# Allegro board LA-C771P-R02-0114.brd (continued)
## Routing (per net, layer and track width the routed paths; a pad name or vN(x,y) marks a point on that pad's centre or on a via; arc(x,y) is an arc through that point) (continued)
PMC_PCIE_WAKE#: length 22.5
  TOP w0.102: QC3.3 85.16,78.31 88.38,75.09 v2(89.97,75.09) 91.21,73.86 96.69,73.86 96.87,74.03 100.15,74.03 100.21,73.97 100.75,73.97 101,74.22 101,75.19 99.78,76.41 RPC5.1 99.78,76.84 100.05,77.11 v3(100.05,77.39)
  BOTTOM w0.102: UC4.F26 100.05,77.78 v3(100.05,77.39)
PMC_PLTRST#: length 118.8
  TOP w0.102: QC2.3 88.83,28.54 v1(88.83,30.25) v3(88.83,31.4) ; UC8.1 UC8.2 79,81.57 79.73,82.3 80.3,82.3 81.03,81.56 RC48.1 81.03,81.04 v3(80.75,80.76)
  IN2 w0.127: v3(80.75,80.76) 80.9,80.76 81.82,79.84 83.48,79.84 83.89,79.43 86.41,79.43 89.48,82.5 93.05,82.5 93.99,83.45 94.88,83.45 95.92,82.41 99.09,82.41 100.55,80.94 v3(100.55,80.28)
  BOTTOM w0.102: v3(100.55,80.28) 100.19,80.65 UC4.F20 ; v3(80.75,80.76) 80.7,80.7 79.83,80.7 79.29,80.16 77.66,80.16 77.04,80.78 74.37,80.78 73.71,80.12 71.65,80.12 70.81,79.28 70.81,76.59 69.94,75.72 69.94,72.93 71.81,71.06 71.81,57.54 63.48,49.21 63.48,45.27 62.27,44.06 62.27,39.78 66.31,35.74 70.16,35.74 71.28,34.63 82.38,34.63 85.14,31.86 88.37,31.86 v3(88.83,31.4)
PMC_PLTRST#_R: length 67.5
  TOP w0.102: v3(70.45,71.07) 71.1,71.07 71.76,70.4 73.8,70.4 77.01,73.61 77.01,75.33 77.28,75.6 77.28,78.34 78.3,79.37 79.13,79.37 80.12,80.36 RC48.2 ; RB30.1 72.8,33.89 v3(72.55,34.14)
  BOTTOM w0.102: v3(72.55,34.14) v2(71.51,34.14) 71.08,34.14 69.96,35.26 66.11,35.26 61.79,39.58 61.79,44.26 63,45.47 63,49.41 71.33,57.74 71.33,70.19 v3(70.45,71.07)
PMC_SLP_S3#: length 138.4
  TOP w0.102: UB1.106 78.27,17.37 78.27,17.37 78.07,17.37 v3(77.18,18.25) ; v3(96.55,20.71) 96.83,20.99 96.83,24.8 95.88,25.75 95.88,28.87 v3(93.99,30.76)
  IN2 w0.127: v3(96.55,20.71) 96.5,20.76 90.66,20.76 89.8,21.62 88.55,21.62 86.91,19.99 86.13,19.99 85.83,19.68 78.63,19.68 77.2,18.25 v3(77.18,18.25)
  BOTTOM w0.102: v3(93.99,30.76) 92.41,32.34 89.6,32.34 87.65,34.29 84.9,34.29 83.27,35.92 71.74,35.92 70.72,36.94 67.17,36.94 65.31,38.79 65.31,40.27 64.05,41.53 64.05,43.32 65.31,44.58 65.31,45.69 66.24,46.62 66.24,48.01 74.56,56.32 74.56,74.23 74.03,74.76 74.03,75.67 75.84,77.48 85.22,77.48 v1(86.71,78.98) 88.62,80.88 91.46,80.88 91.59,80.75 92.39,80.75 93.08,80.07 94.33,80.07 95.02,79.38 96.22,79.38 96.65,78.95 97.15,78.95 97.31,79.11 98.01,79.11 98.15,79.26 98.3,79.26 98.45,79.1 98.62,79.1 98.71,79.12 98.81,79.19 98.89,79.32 98.94,79.32 99.51,79.89 UC4.D22
PMC_SLP_S4#: length 111.6
  TOP w0.102: RB22.1 83.67,24.99 84.74,24.99 85.2,25.45 85.2,26.08 84.6,26.68 v1(84.6,27.5) 84.6,32.53 85.71,33.64 86.49,33.64 v3(86.82,33.31)
  IN2 w0.127: v3(99.83,79.42) 99.76,79.42 98.7,80.48 98.7,81.4 98,82.1 95.69,82.1 95.21,82.58 94.02,82.58 93.43,82 89.69,82 86.62,78.93 83.68,78.93 83.27,79.33 82.41,79.33 82.2,79.13 76.1,79.13 v3(75.45,78.48)
  BOTTOM w0.102: v3(86.82,33.31) 86.27,32.75 85.04,32.75 82.69,35.11 71.48,35.11 70.36,36.23 67.03,36.23 64.4,38.86 64.4,40.06 63.59,40.87 63.59,43.51 64.85,44.77 64.85,45.98 65.78,46.91 65.78,48.24 74.1,56.56 74.1,74.05 73.58,74.57 73.58,75.86 75.45,77.74 v3(75.45,78.48) ; UC4.F22 99.83,79.53 v3(99.83,79.42)
PMON: length 3.8
  TOP w0.102: PC217.2 203.12,69.87 203.16,69.83 v2(203.12,69.83)
  TOP w0.254: v3(203.74,71.95) 203.74,71.43 PC217.2
  BOTTOM w0.203: v3(203.74,71.95) 203.56,71.78 PU1.9
PWR_LED#: length 82
  TOP w0.102: LED1.1 13.75,2.25 v2(13.75,4.2) 13.75,4.43 14.26,4.94 C9.1 v3(13.5,5.47) ; R12.1 v3(23.55,6.99) ; UB1.92 76.53,10.54 77.05,10.02 77.05,7.19 76.83,6.96 76.83,4.61 v3(76.18,3.97)
  IN2 w0.127: v3(76.18,3.97) 76.18,3.47 74.3,1.59 31.91,1.59 29.35,4.15 29.35,5.21 28.21,6.36 24.19,6.36 v3(23.55,6.99) 23.27,6.99 22.26,5.98 14,5.98 v3(13.5,5.47)
RJ45_RX1+: length 8.2
  IN2 w0.127: JLAN1.3 14.78,70.12 14.99,69.91 15.48,69.91 15.7,69.68 15.7,68.64 16.04,68.31 16.92,68.31 17.28,68.67 17.28,68.89 17.02,69.15 16.85,69.15 v3(16.54,68.84)
  BOTTOM w0.102: TL1.15 17.58,68.82 17.15,69.25 16.7,69.25 16.54,69.1 v3(16.54,68.84)
RJ45_RX1-: length 8.2
  IN2 w0.127: JLAN1.6 15.57,68.07 15.77,67.88 17.1,67.88 17.71,68.49 17.71,69.07 17.2,69.58 16.82,69.58 v3(16.54,69.86)
  BOTTOM w0.102: v3(16.54,69.86) 16.75,69.66 17.15,69.66 17.58,70.09 TL1.16
RJ45_TX0+: length 19.3
  IN2 w0.127: v3(15.64,61.36) 15.71,61.43 16.39,61.43 18.73,63.76 18.73,71.81 17.96,72.58 15.37,72.58 JLAN1.1
  BOTTOM w0.102: v3(15.64,61.36) 15.81,61.53 16.97,61.53 17.31,61.2 TL1.9
RJ45_TX0-: length 19.3
  IN2 w0.127: JLAN1.2 17.78,72.15 18.3,71.64 18.3,63.94 16.21,61.86 15.78,61.86 15.64,62 v3(15.64,62.3)
  BOTTOM w0.102: TL1.10 17.39,62.47 16.86,61.93 15.86,61.93 15.64,62.15 v3(15.64,62.3)
RTC_RST#: length 79.9
  BOTTOM w0.102: CLRP2.1 59.37,43.48 59.37,45.26 60.58,46.46 60.58,50.44 68.88,58.74 68.88,68.98 67.44,70.42 67.18,70.42 65.68,71.91 65.68,76.64 65.75,76.72 65.75,78 70.54,82.79 72.6,82.79 73.26,83.45 v2(79.46,83.45) 84.84,83.45 88.75,87.36 88.94,87.36 RC83.1 89.23,87.65 RC54.2 91.19,86.6 92.75,86.6 RC49.2 CC25.1 94.67,85.83 94.67,85.3 95.26,84.71 96.38,84.71 96.73,84.36 97.47,84.36 97.65,84.54 98,84.54 98.02,84.53 98.1,84.45 98.24,84.45 98.36,84.46 98.46,84.56 UC4.C12
RTC_TEST#: length 82.1
  BOTTOM w0.102: UC4.C11 98.28,85.22 97.9,84.85 97.57,84.85 97.37,84.64 96.98,84.64 96.49,85.12 96.02,85.12 95.87,84.97 95.33,84.97 95.08,85.22 95.08,86.2 94.54,86.74 94.54,88.38 94.17,88.75 92.09,88.75 RC47.2 CC24.1 RC54.1 89.24,88.57 RC84.1 88.78,88.1 88.63,88.1 84.6,84.08 v2(82.98,84.08) 69.22,84.08 68.71,83.56 68.28,83.56 65.14,80.42 65.14,76.97 65.07,76.9 65.07,71.66 66.92,69.81 67.19,69.81 68.27,68.73 68.27,58.99 59.97,50.69 59.97,46.77 58.76,45.57 58.76,44.28 CLRP1.1
SATA_PRX_C_DTX_N0: length 9.1
  BOTTOM w0.102: CO7.2 204.61,32.6 v4(206.69,32.6) 207.25,32.6 210.58,35.93 210.9,35.93 JHDD1.5
SATA_PRX_C_DTX_N1: length 6.9
  BOTTOM w0.102: CO6.2 219.84,97.92 v4(220.55,97.92) 221.54,97.92 221.55,97.91 222.08,97.91 222.1,97.92 224.18,97.92 224.39,98.13 224.69,98.43 225.33,98.43 JODD1.5
SATA_PRX_C_DTX_P0: length 9.1
  BOTTOM w0.102: CO1.2 204.61,32.82 v4(205.27,32.82) 207.16,32.82 210.49,36.15 210.9,36.15 JHDD1.6
SATA_PRX_C_DTX_P1: length 6.9
  BOTTOM w0.102: CO8.2 219.85,98.14 220.28,98.14 220.29,98.15 220.82,98.15 220.83,98.14 v4(221.82,98.14) 224.1,98.14 224.6,98.64 225.33,98.64 JODD1.6
SATA_PRX_DTX_N0: length 139
  IN2 w0.089: 120.35,83.19 120.35,83.18 120.35,83.13 120.09,82.88 116.65,82.88 116.48,83.04 116.48,83.15 v3(116.64,83.31)
  IN2 w0.127: v3(177.15,36.09) 177.35,36.29 177.74,36.29 178.01,36.56 178.01,44.13 180.18,46.3 180.18,52.22 177.77,54.64 177.77,56.38 170.76,63.39 170.76,80.53 167.59,83.7 166.74,83.7 163.69,86.75 153.87,86.75 153.2,87.42 150.29,87.42 150.05,87.18 143.04,87.18 140.89,85.03 123.26,85.03 122.66,84.43 121.59,84.43 120.35,83.19
  BOTTOM w0.102: CO7.1 202.99,32.38 202.69,32.38 201.28,30.97 193.05,30.97 191.48,32.53 188.41,32.53 187,33.94 181.09,33.94 180.3,34.73 178.72,36.31 177.36,36.31 v3(177.15,36.09) ; UC4.AV16 116.27,82.93 v3(116.64,83.31)
SATA_PRX_DTX_N1: length 119.3
  IN2 w0.089: v3(117.9,83.33) 117.75,83.33 117.65,83.43 117.65,83.83 117.72,83.9 117.72,85.49 118.06,85.83 118.06,86.71 118.34,86.99 118.34,88.08 119.22,88.97 119.22,89.33 119.61,89.71 120.09,89.71 120.13,89.67 120.15,89.67
  IN2 w0.127: 120.15,89.67 120.89,89.67 123.5,92.29 130.8,92.29 133.24,94.72 139.59,94.72 144.57,89.74 148.99,89.74 149.75,90.51 161.48,90.51 161.83,90.15 165.01,90.15 167.85,87.32 169.17,87.32 170.94,85.56 173.15,85.56 175.52,87.93 177.24,87.93 182.06,92.76 209.6,92.76 214.91,98.07 217.2,98.07 217.39,97.88 v3(217.39,97.68)
  BOTTOM w0.102: v3(117.9,83.33) 117.69,83.12 UC4.BA16 ; v3(217.39,97.68) 217.66,97.95 218.24,97.95 CO6.1
SATA_PRX_DTX_P0: length 139
  IN2 w0.089: v3(116.01,83.24) 116.22,83.24 116.29,83.17 116.29,82.97 116.57,82.69 120.17,82.69 120.48,83 120.53,83 120.54,83
  IN2 w0.127: v3(177.15,36.83) 177.42,36.56 177.63,36.56 177.74,36.67 177.74,44.24 179.92,46.41 179.92,52.11 177.5,54.53 177.5,56.27 170.49,63.28 170.49,80.42 167.48,83.44 166.63,83.44 163.58,86.48 153.76,86.48 153.09,87.15 150.4,87.15 150.16,86.91 143.15,86.91 141,84.76 123.37,84.76 122.77,84.16 121.7,84.16 120.54,83
  BOTTOM w0.102: CO1.1 203.23,32.75 203.08,32.6 202.6,32.6 201.19,31.19 193.14,31.19 191.57,32.75 188.5,32.75 187.09,34.16 181.18,34.16 180.39,34.95 180.39,34.95 178.81,36.52 177.46,36.52 v3(177.15,36.83) ; v3(116.01,83.24) 115.56,82.79 UC4.AU16
SATA_PRX_DTX_P1: length 119.3
  IN2 w0.089: v3(117.28,83.35) 117.46,83.53 117.46,83.91 117.53,83.98 117.53,85.57 117.87,85.91 117.87,86.79 118.15,87.07 118.15,88.16 119.03,89.04 119.03,89.41 119.53,89.9 120.09,89.9 120.13,89.94 120.15,89.94
  IN2 w0.127: 120.15,89.94 120.78,89.94 123.39,92.55 130.69,92.55 133.13,94.99 139.7,94.99 144.68,90.01 148.88,90.01 149.64,90.78 161.59,90.78 161.94,90.42 165.12,90.42 167.96,87.59 169.28,87.59 171.05,85.82 173.04,85.82 175.41,88.2 177.13,88.2 181.95,93.02 209.49,93.02 214.8,98.34 217.28,98.34 v3(217.39,98.45)
  BOTTOM w0.102: v3(217.39,98.45) 217.68,98.16 218.28,98.16 CO8.1 ; UC4.AY16 116.98,83.05 v3(117.28,83.35)
SATA_PTX_C_DRX_N0: length 8.4
  BOTTOM w0.102: CO3.2 204.61,30.53 v4(205.21,30.53) 207.9,30.53 209.71,32.34 210.91,32.34 JHDD1.3
SATA_PTX_C_DRX_N1: length 7.1
  BOTTOM w0.102: JODD1.3 225.33,94.83 223.74,94.83 222.97,94.07 v4(221.79,94.07) 220.79,94.07 220.78,94.08 220.25,94.08 220.24,94.07 219.93,94.07 CO5.2
SATA_PTX_C_DRX_P0: length 8.4
  BOTTOM w0.102: JHDD1.2 210.9,32.13 209.8,32.13 207.99,30.31 v4(206.79,30.31) 204.61,30.31 CO2.2
SATA_PTX_C_DRX_P1: length 7.1
  BOTTOM w0.102: JODD1.2 225.33,94.62 223.83,94.62 223.06,93.85 222.07,93.85 222.06,93.84 221.53,93.84 221.51,93.85 v4(220.52,93.85) 219.93,93.85 CO4.2
SATA_PTX_DRX_N0: length 138.6
  IN2 w0.089: 121.7,86.07 121.69,86.07 121.65,86.11 121.33,86.11 120.56,86.88 120.12,86.88 119.92,86.67 119.92,86.56 120.04,86.44 v3(120.3,86.44)
  IN2 w0.127: v3(177.58,34.16) 177.58,33.94 177.77,33.75 178,33.75 178.54,34.3 178.54,43.92 180.69,46.07 180.69,52.43 178.28,54.85 178.28,56.62 171.52,63.37 171.52,80.49 167.8,84.21 166.95,84.21 163.9,87.26 154.08,87.26 153.41,87.92 150.08,87.92 149.84,87.69 142.83,87.69 140.74,85.6 123.74,85.6 123.27,86.07 121.7,86.07
  BOTTOM w0.102: UC4.BG7 120.17,87.2 120.08,87.2 120,87.12 120,86.52 120.08,86.44 v3(120.3,86.44) ; v3(177.58,34.16) 177.58,33.94 177.79,33.73 179.88,33.73 180.4,33.21 186.85,33.21 188.15,31.91 191.17,31.91 192.77,30.31 203.13,30.31 203.23,30.41 CO3.1
SATA_PTX_DRX_N1: length 116.8
  IN2 w0.089: 121.23,88.39 121.21,88.37 121.16,88.37 120.76,87.98 119.23,87.98 118.91,87.65 118.91,87.18 119.16,86.93 119.16,86.17 119.44,85.89 119.64,85.89 119.86,85.67 119.86,85.41 v3(120.02,85.25)
  IN2 w0.127: 121.23,88.39 121.86,89.03 123.52,89.03 124.15,89.66 130.42,89.66 134.67,93.91 138.8,93.91 143.74,88.97 149.31,88.97 149.55,89.21 154.03,89.21 154.55,89.73 156.12,89.73 156.48,89.38 164.69,89.38 167.52,86.55 168.85,86.55 170.62,84.78 173.53,84.78 175.43,86.69 177.16,86.69 182.35,91.88 217.51,91.88 218.56,92.93 218.56,93.75 218.18,94.13 217.82,94.13 v3(217.65,94.3)
  BOTTOM w0.102: v3(217.65,94.3) 217.86,94.09 218.21,94.09 CO5.1 ; UC4.BF10 120.02,85.55 v3(120.02,85.25)
SATA_PTX_DRX_P0: length 138.6
  IN2 w0.089: 121.7,86.34 121.69,86.34 121.65,86.3 121.41,86.3 120.64,87.07 120.05,87.07 119.73,86.75 119.73,86.37 v3(119.64,86.29)
  IN2 w0.127: v3(177.58,33.37) 177.69,33.49 178.11,33.49 178.81,34.18 178.81,43.81 180.96,45.96 180.96,52.54 178.54,54.96 178.54,56.73 171.79,63.48 171.79,80.6 167.91,84.48 167.06,84.48 164.01,87.52 154.19,87.52 153.53,88.19 149.97,88.19 149.73,87.95 142.72,87.95 140.63,85.87 123.85,85.87 123.38,86.34 121.7,86.34
  BOTTOM w0.102: v3(119.64,86.29) 119.78,86.43 119.78,87.21 119.89,87.31 UC4.BF6 ; CO2.1 202.99,30.09 192.68,30.09 191.08,31.7 188.06,31.7 186.76,32.99 180.31,32.99 179.79,33.51 177.72,33.51 v3(177.58,33.37)
SATA_PTX_DRX_P1: length 116.6
  IN2 w0.089: 121.04,88.58 121.02,88.56 121.02,88.51 120.68,88.17 119.15,88.17 118.71,87.73 118.71,87.1 118.97,86.85 118.97,86.09 119.36,85.7 119.56,85.7 119.67,85.59 119.67,85.43 119.53,85.29 v3(119.42,85.29)
  IN2 w0.127: 121.04,88.58 121.75,89.29 123.4,89.29 124.04,89.92 130.31,89.92 134.56,94.18 138.91,94.18 143.85,89.24 149.2,89.24 149.44,89.47 153.92,89.47 154.44,90 156.23,90 156.59,89.65 164.8,89.65 167.64,86.81 168.96,86.81 170.73,85.05 173.42,85.05 175.32,86.95 177.05,86.95 182.24,92.15 217.4,92.15 218.29,93.04 218.29,93.64 218.07,93.86 217.82,93.86 217.82,93.86 217.76,93.86 217.65,93.76 v3(217.65,93.55)
  BOTTOM w0.102: v3(217.65,93.55) 217.97,93.87 218.17,93.87 CO4.1 ; UC4.BD10 119.42,85.45 v3(119.42,85.29)
SATA_RCOMPN: length 1.4
  TOP w0.254: RC16.1 115.31,81.82 v3(115.31,82.33)
  BOTTOM w0.254: v3(115.31,82.33) 114.85,81.86 UC4.AT18
SATA_RCOMPP: length 1.4
  TOP w0.254: RC16.2 115.98,81.76 v3(115.98,82.31)
  BOTTOM w0.254: UC4.AU18 115.56,81.89 v3(115.98,82.31)
SD_CD#: length 12.8
  TOP w0.102: v3(54.07,13.23) 54.07,13.46 v2(53.65,13.88) 51.43,13.88 50.78,13.23 UR1.21
  BOTTOM w0.102: v3(54.07,13.23) 58.37,17.53 JSD1.10
SD_CLK: length 24.8
  TOP w0.102: v3(46.7,7.48) 46.7,5.16 v2(46.79,5.06) 47.45,5.06 47.68,5.29 CR9.1 47.18,6.38 47.18,8.05 RR4.1
  BOTTOM w0.102: JSD1.5 44.17,20.78 43.97,20.98 43.23,20.98 42.98,20.74 42.98,11.69 46.7,7.97 v3(46.7,7.48)
SD_CLK_R: length 2.3
  TOP w0.102: RR4.2 46.59,9.55 v2(46.59,10.32) 46.68,10.41 UR1.14
SD_CMD: length 20.6
  TOP w0.102: v2(48.78,7.1) 48.88,7.2 v3(48.88,7.68) RR5.2
  BOTTOM w0.102: v3(48.88,7.68) 48.88,8.98 51.65,11.74 51.65,12.82 51.75,12.93 52.37,12.93 52.47,13.03 52.47,13.38 52.37,13.48 51.75,13.48 51.65,13.59 51.65,13.94 51.75,14.04 52.37,14.04 52.47,14.14 52.47,14.5 52.37,14.6 51.75,14.6 51.65,14.7 51.65,15.06 51.75,15.16 52.37,15.16 52.47,15.26 52.47,15.62 52.37,15.72 51.75,15.72 51.65,15.82 51.65,16.37 51.85,16.58 53.05,16.58 53.22,16.75 53.22,17 53.04,17.18 51.85,17.18 51.67,17.36 JSD1.2
SD_CMD_R: length 2.7
  TOP w0.102: UR1.16 47.68,10.88 48.32,10.24 v2(48.33,10.24) 48.88,9.68 RR5.1
SD_D0: length 22.7
  TOP w0.102: RR3.2 v3(45.89,7.37) 45.58,7.07 v2(45.32,7.07)
  BOTTOM w0.102: JSD1.7 39.25,17.36 39.15,17.26 38.01,17.26 37.93,17.18 37.93,16.78 38.01,16.7 40.1,16.7 40.18,16.62 40.18,16.22 40.1,16.14 38.01,16.14 37.93,16.06 37.93,15.66 38.01,15.58 39.15,15.58 39.25,15.48 39.25,14.1 45.89,7.47 v3(45.89,7.37)
SD_D0_R: length 7.7
  TOP w0.102: UR1.13 46.18,10.95 45.36,10.13 45.36,9.53 45.64,9.25 RR3.1 46.06,9.25 46.41,8.9 46.41,7.96 46.29,7.84 46.29,6.65 v2(44.97,5.32)
SD_D1: length 21.9
  TOP w0.102: v2(43.34,4.96) 44.89,6.51 v3(44.89,7.5) RR2.2
  BOTTOM w0.102: JSD1.8 37.55,17.52 37.45,17.41 36.35,17.41 36.24,17.31 36.24,16.96 36.35,16.86 37.45,16.86 37.55,16.75 37.55,15.12 41.66,11.01 41.66,9 43.16,7.5 v3(44.89,7.5)
SD_D1_R: length 3.5
  TOP w0.102: UR1.12 45.04,12.23 44.96,12.15 44.96,10.45 v2(44.76,10.25) 44.71,10.19 44.71,9.43 RR2.1
SD_D2: length 18.6
  TOP w0.102: v3(51.41,7.32) 51.71,7.32 51.98,7.58 v2(51.98,8.31) 51.87,8.42 50.96,8.42 RR7.2
  BOTTOM w0.102: v3(51.41,7.32) 51.66,7.57 51.66,7.71 51.39,7.98 51.39,8.22 51.56,8.38 51.79,8.38 52.06,8.11 52.2,8.11 52.45,8.36 52.45,8.5 52.09,8.87 52.09,9.1 52.25,9.26 52.49,9.26 52.85,8.9 52.99,8.9 53.25,9.15 53.25,14.61 56.67,18.04 JSD1.9
SD_D2_R: length 4
  TOP w0.102: RR7.1 v2(50.88,10.3) 50.88,10.38 50.44,10.81 48.94,10.81 48.68,11.07 UR1.18
SD_D3: length 21.9
  TOP w0.102: RR6.2 v3(49.88,7.63) 49.88,6.4 v2(50.81,5.47)
  BOTTOM w0.102: JSD1.1 54.17,16.66 52.89,15.38 52.89,10.64 52.59,10.34 52.44,10.34 51.84,10.95 51.6,10.95 51.44,10.78 51.44,10.55 52.05,9.94 52.05,9.8 51.8,9.55 51.65,9.55 51.04,10.17 50.8,10.17 50.64,10 50.64,9.77 51.26,9.15 51.26,9.01 51.01,8.76 50.86,8.76 50.36,9.26 50.13,9.26 49.97,9.1 49.97,8.87 50.47,8.36 50.47,8.22 v3(49.88,7.63)
SD_D3_R: length 5.6
  TOP w0.102: UR1.17 48.18,11.04 48.77,10.46 49.49,10.46 49.88,10.07 RR6.1 50.38,8.75 50.38,7.88 50.55,7.71 v2(50.55,7.27)
SD_GPIO1: length 2.4
  TOP w0.254: UR1.19 50.5,12.23 v2(50.66,12.07) 51.16,11.57 RR8.1
SD_WP: length 29
  TOP w0.102: v2(51.95,13.32) 51.36,12.73 v3(50.3,12.73) UR1.20
  BOTTOM w0.102: v3(50.3,12.73) 50.3,12.43 47.4,9.53 47.4,7.02 47.25,6.87 43.29,6.87 41.31,8.85 41.31,10.86 35.75,16.42 JSD1.11
SKU_STRAP1: length 3
  TOP w0.102: v3(116.59,74.4) 116.94,74.06 117.11,74.06 RC34.2 117.96,73.21 RC81.1
  BOTTOM w0.102: UC4.AV34 116.27,74.05 116.59,74.38 v3(116.59,74.4)
SKU_STRAP2: length 3.8
  TOP w0.102: RC33.2 120.48,75.37 120.07,74.96 119.8,74.96 RC29.1 119.29,74.53 118.88,74.12 118.32,74.12 v3(118.04,74.4)
  BOTTOM w0.102: UC4.BA34 117.69,74.05 v3(118.04,74.4)
SKU_STRAP3: length 7
  TOP w0.102: v2(122.63,73.34) 122.37,73.08 121.89,73.08 RC28.1 120.51,73.76 120.22,74.05 119.13,74.05 118.55,73.46 RC32.2 118.09,73.78 118.09,73.92 117.99,74.02 117.68,74.02 v3(117.3,74.4)
  BOTTOM w0.102: UC4.AY34 116.98,74.08 v3(117.3,74.4)
SOC_ENBKL: length 84.4
  TOP w0.102: UB1.97 78.72,13.77 77.94,14.55 77.94,15.11 72.73,20.33 v3(72.73,23.33)
  IN2 w0.127: v3(72.73,23.33) 72.73,24.42 64.68,32.47 64.68,32.8 v3(64.14,33.33)
  BOTTOM w0.102: v3(64.14,33.33) 63.56,33.33 56.52,40.37 56.52,45.15 58.68,47.31 58.68,51.23 65.9,58.45 65.9,67.9 64.88,68.92 v2(64.24,68.92) 62.29,68.92 60.28,70.93 60.28,76.22 59.94,76.56 59.62,76.56 58.83,77.35 RC10.2
SOC_ENVDD: length 88.1
  TOP w0.102: v3(85.24,29.43) 85.3,29.38 85.3,26.63 85.66,26.27 85.66,25.26 84.84,24.44 84.23,24.44 83.82,24.03 82.12,24.03 81.46,23.37 UB1.121
  BOTTOM w0.102: v3(85.24,29.43) 85.24,29.43 85,29.19 75.37,29.19 v2(74.63,29.93) 74.07,30.49 70.54,30.49 67.65,33.38 64.83,33.38 64.43,33.79 63.43,33.79 56.75,40.47 56.75,45.06 58.9,47.21 58.9,51.14 66.12,58.36 66.12,58.81 66.12,68 62.26,71.86 62.26,76.64 63.28,77.65 RC13.2
SOC_I2C0_CLK: length 3.2
  BOTTOM w0.102: T17.1 122.95,77.02 122.59,76.67 122.19,76.67 121.81,77.04 121.43,77.04 121.22,77.26 120.96,77.26 120.81,77.11 120.65,77.11 120.5,76.97 UC4.BG28
SOC_I2C0_DATA: length 3
  BOTTOM w0.102: T16.1 122.84,76.2 122.57,76.46 122.1,76.46 121.78,76.79 121.25,76.79 UC4.BH28
SOC_PCIE_WAKE#: length 188.9
  TOP w0.102: v3(55.72,78.04) 56.92,79.23 59.8,79.23 60.23,78.8 v1(61.17,78.8) 62.6,78.8 63.06,78.34 63.06,71.68 64.2,70.53 65.34,70.53 66.07,69.81 68.1,69.81 68.19,69.72 73.44,69.72 77.24,73.52 77.24,75.24 77.53,75.54 77.53,78.27 78.4,79.14 79.22,79.14 80.29,80.21 81.6,80.21 82.08,79.73 82.08,78.97 83.57,77.48 RC27.1 84.46,77.48 85.4,76.54 QC3.1
  IN1 w0.127: v3(175.04,88.91) 174.72,88.59 174.66,88.59 172.73,86.66 171.43,86.66 171.11,86.98 171.11,87.6 170.31,88.4 169.42,88.4 168.72,87.7 167.94,87.7 165.94,89.7 161.85,89.7 161.56,89.4 156.42,89.4 155.93,89.9 154.4,89.9 153.88,89.38 149.89,89.38 143.6,95.67 143.6,96.25 139.17,100.69 126.3,100.69 125.06,99.45 120.78,99.45 120.26,99.97 87.51,99.97 84.38,96.85 78.3,96.85 70.31,88.86 66.46,88.86 65.65,88.06 62.48,88.06 60.45,86.03 59.26,86.03 55.7,82.46 55.7,80.37 55.44,80.11 55.44,79.12 55.72,78.85 v3(55.72,78.04)
  BOTTOM w0.102: v3(175.04,88.91) 174.6,88.47 RM3.1
SOC_SPI_CLK: length 10.9
  BOTTOM w0.102: RPC7.5 90.52,82.92 90.56,82.87 91.68,82.87 v2(91.76,82.8) 92.2,82.8 92.4,82.6 92.4,81.83 92.67,81.56 94.28,81.56 95.19,80.65 97.99,80.65 98.05,80.59 98.11,80.53 98.32,80.53 98.39,80.6 98.47,80.66 98.56,80.66 98.57,80.66 98.63,80.66 98.73,80.62 98.83,80.53 98.92,80.29 98.92,79.88 UC4.C22
SOC_SPI_CS0#: length 9.4
  BOTTOM w0.102: UC4.C23 98.45,79.52 98.14,79.52 98,79.67 97.97,79.67 97.96,79.67 97.37,79.67 97.22,79.83 96.42,79.83 96.31,79.72 v1(95.69,79.72) 94.97,79.72 94.42,80.27 93.16,80.27 92.48,80.95 91.89,80.95 91.43,81.42 RPC7.8
SOC_SPI_MISO: length 9
  BOTTOM w0.102: RPC7.7 91.48,81.92 92.07,81.33 ; 92.07,81.33 92.24,81.16 92.56,81.16 93.24,80.48 94.5,80.48 94.95,80.03 95.4,80.03 97.3,80.03 97.46,79.88 98.22,79.88 UC4.B22 ; 92.07,81.33 v1(92.07,81.33)
SOC_SPI_MOSI: length 8.6
  BOTTOM w0.102: RPC7.6 90.13,82.39 91.56,82.39 92.59,81.36 94.19,81.36 95.11,80.44 97.11,80.44 97.76,80.44 UC4.A21
SPI_CLK: length 80.1
  TOP w0.102: RC53.1 52.55,36.76 52.29,37.02 UC10.6 52.29,39.19 55.05,41.94 RPC8.4 56.8,41.54 57.39,40.95 61.72,40.95 62.77,39.91 v3(62.85,39.91)
  BOTTOM w0.102: RPC7.4 88.1,82.92 87.26,82.08 86.04,82.08 85.38,81.42 84.73,81.42 83.59,80.27 v2(81.64,80.27) 81.57,80.2 80,80.2 79.49,79.68 77.46,79.68 76.84,80.3 74.57,80.3 73.91,79.64 71.85,79.64 71.29,79.08 71.29,76.39 70.42,75.52 70.42,73.13 72.3,71.26 72.3,57.34 63.97,49.01 63.97,45.07 62.75,43.86 62.75,40 v3(62.85,39.91)
SPI_CS0#: length 69.3
  TOP w0.102: v3(65.27,47.73) 64.99,48.02 v1(63.93,48.02) 62.5,48.02 59.28,44.8 57.3,44.8 RC50.2 56.7,45.35 56.37,45.02 56.37,44.48 56.8,44.05 RPC8.1 55.65,43.44 54.83,44.26 UC10.1
  BOTTOM w0.102: v3(65.27,47.73) 65.3,47.76 65.3,48.48 73.62,56.79 73.62,71.8 71.74,73.68 71.74,74.97 73.64,76.87 73.87,76.87 74.64,77.63 74.64,78.5 75.12,78.98 76.29,78.98 77.31,77.97 85.02,77.97 88.47,81.42 RPC7.1
SPI_HOLD#: length 5.8
  TOP w0.102: v2(53.57,36.85) 53.57,37.11 53.56,37.11 UC10.7 53.56,39.57 54.26,40.27 RC51.2
SPI_MISO: length 71.1
  TOP w0.102: UC10.2 53.56,43.75 54.38,42.94 RPC8.2 57.19,42.94 57.39,43.14 57.39,44.04 57.65,44.3 59.46,44.3 v1(62.27,47.11) 62.7,47.53 64.52,47.53 v3(65.03,47.02)
  BOTTOM w0.102: RPC7.2 88.29,81.92 86.78,80.41 84.96,80.41 82.99,78.45 77.51,78.45 76.49,79.46 74.92,79.46 74.16,78.7 74.16,77.83 73.67,77.35 73.44,77.35 71.26,75.17 71.26,73.48 73.13,71.6 73.13,56.99 64.81,48.66 64.81,47.25 v3(65.03,47.02)
SPI_MOSI: length 79.4
  TOP w0.102: v3(63.55,39.86) 63.55,39.87 v1(62.48,40.94) 61.99,41.44 57.69,41.44 57.31,41.82 57.31,42.3 57.17,42.44 RPC8.3 54.28,42.44 51.02,39.19 UC10.5
  BOTTOM w0.102: v3(63.55,39.86) 63.55,39.91 63.24,40.22 63.24,43.66 64.45,44.87 64.45,48.81 72.78,57.14 72.78,71.46 70.9,73.33 70.9,75.32 71.78,76.19 71.78,78.88 72.05,79.16 74.11,79.16 74.77,79.82 76.64,79.82 77.65,78.8 82.1,78.8 82.7,79.4 83.44,79.4 84.98,80.93 86.8,80.93 88.28,82.42 RPC7.3
SPI_WP#: length 4.2
  TOP w0.102: v2(53.86,49.46) RC52.2 53.6,48.27 52.29,46.97 UC10.3
SPK_L1-: length 246.6
  TOP w0.203: v3(28.81,25.15) 28.71,25.15 28.23,24.68 UA1.43
  BOTTOM w1.016: LA1.1 183.04,89.61 182.56,89.12 v2(182.56,85) 180.44,85 172.13,76.68 172.13,32.39 177.68,26.83 177.68,18.49 163.75,4.56 114.51,4.56 110.42,8.64 102.25,8.64 97.86,13.04 80.57,13.04 79.6,12.07 75.98,12.07 75.34,12.71 69.33,12.71 68.54,13.5 65.19,13.5 62.45,16.23 62.45,17.28 62.45,17.28 62.45,20.82 59.19,24.08 56.49,24.08 55.21,25.36 34.97,25.36 34.05,26.27 30.59,26.27 30.49,26.17
  vias: v3(29.42,25.18)
SPK_L1-_CONN:
  vias: v3(184.44,87.63)
SPK_L2+: length 254.2
  TOP w0.203: UA1.42 28.54,24.28 v3(28.73,24.47)
  BOTTOM w1.016: LA2.1 189.59,88.79 v2(189.59,86.8) 189.59,84.45 187.72,82.58 184.31,82.58 183.42,83.47 180.71,83.47 173.4,76.15 173.4,33.23 178.95,27.67 178.95,17.91 164.5,3.46 164.47,3.49 164.27,3.29 113.98,3.29 109.89,7.37 101.73,7.37 97.33,11.77 81.1,11.77 80.13,10.8 75.45,10.8 74.82,11.44 68.81,11.44 68.02,12.23 64.66,12.23 61.1,15.79 61.1,20.38 58.67,22.81 55.96,22.81 54.68,24.09 34.44,24.09 33.52,25 31.43,25 30.94,24.52
  vias: v3(29.37,24.47)
SPK_L2+_CONN:
  vias: v3(187.9,87.66)
SRN: length 29.1
  TOP w0.102: v2(192.59,78.98) 192.53,78.98 v3(192.04,78.49)
  IN2 w0.254: v3(200.52,64.78) 200.79,65.06 202.45,65.06 203.54,66.15 203.54,69.59 202.73,70.4 202.73,72.1 201.84,72.98 199.99,72.98 198.34,74.63 198.34,75.38 197.67,76.06 195.27,76.06 193.14,78.19 192.35,78.19 v3(192.04,78.49)
  BOTTOM w0.203: v3(200.52,64.78) 201.07,64.78 201.39,65.1 PC222.1 200.53,65.46 PC221.1 200.5,65.49 PR227.2
  BOTTOM w0.254: v3(192.04,78.49) 192.04,78.32 192.31,78.05 PR221.3
SRP: length 29
  TOP w0.102: v3(192.1,77.42) 192.34,77.17 v2(192.74,77.17)
  IN2 w0.254: v3(192.1,77.42) 192.35,77.67 193.02,77.67 195.07,75.62 197.47,75.62 197.92,75.17 197.92,74.51 199.83,72.6 201.68,72.6 202.34,71.94 202.34,70.24 203.16,69.43 203.16,66.31 202.34,65.49 200.32,65.49 v3(199.61,64.78)
  BOTTOM w0.203: v3(199.61,64.78) 199.02,64.78 198.74,65.06 PC223.1 PC221.2 199.61,65.49 PR226.2
  BOTTOM w0.254: PR221.2 191.76,78.05 192.1,77.72 v3(192.1,77.42)
SUSP: length 21.5
  TOP w0.254: Q3.2 163.47,42.46 v2(163.47,42.99) Q2.1 161.58,46.22 RQ5.1 161.4,44.76 160.59,43.95 158.96,43.95 Q5.2 157.85,45.06 152.89,45.06 Q4.2
SUSP#: length 227.1
  TOP w0.203: UB1.116 78.51,21.37 78.16,21.72
  TOP w0.254: RQ2.1 v3(193.77,27.63) 194.14,27.26 194.14,25.89 193.84,25.59 RQ1.2 ; RQ3.2 47.68,67.24 47.68,65.21 47.99,64.91 RQ4.2 48.27,64.91 48.29,64.89 48.29,64.46 50.27,62.47 v3(50.28,62.47) ; v3(74.81,22.56) 75.36,22.01 77.88,22.01 78.16,21.72 ; PR411.1 156.16,33.61 v3(156.42,33.61) ; Q2.2 165.55,44.38 165.48,44.32 RQ8.1 164.55,43.72 164.12,43.29 164.12,41.13 162.03,39.05 157.44,39.05 v3(156.78,38.39) 156.78,38.11 158.81,36.08 v2(167.16,36.08) 171.41,36.08 179.64,27.85 v3(184.36,27.85)
  IN1 w0.254: v3(193.77,27.63) 193.16,27.01 187.56,27.01 186.72,27.85 v3(184.36,27.85)
  IN2 w0.254: v3(156.78,38.39) 157.34,37.83 157.34,35.54 156.34,34.55 156.34,33.7 v3(156.42,33.61) 158.13,31.91 158.13,29.16 156.16,27.19 154.01,27.19 152.68,25.86 150.61,25.86 149.24,24.49 117.64,24.49 116.19,25.94 106.71,25.94 104.96,27.69 96.65,27.69 96.37,27.97 89.16,27.97 87.86,26.68 81.81,26.68 78.94,23.81 77.43,23.81 76.18,22.56 v3(74.81,22.56) 71.49,22.56 70.09,23.96 69.64,23.96 68.74,24.86 68.74,25.49 62.68,31.55 62.68,37.09 60.55,39.22 60.55,42.75 61.11,43.31 61.11,51.71 61.02,51.8 61.02,51.82 55.33,57.51 55.33,59.27 52.15,62.44 50.25,62.44 v3(50.28,62.47)
SYSON: length 104
  TOP w0.203: v3(75.85,15.68) 77.73,13.81 UB1.95
  TOP w0.254: v3(105.34,16.49) v2(105.34,26.38) 105.34,26.91 v3(105.92,27.49) ; PR410.1 v3(156.28,29.98)
  IN2 w0.254: v3(105.34,16.49) 105.34,16.49 104.52,16.49 102.7,14.66 94.04,14.66 91.27,17.43 88.95,17.43 88.35,16.82 84.5,16.82 83.98,17.34 78.93,17.34 77.96,16.38 76.55,16.38 v3(75.85,15.68) ; v3(105.92,27.49) 106.61,26.8 115.93,26.8 117.86,24.88 149.09,24.88 150.45,26.24 152.52,26.24 153.85,27.57 156,27.57 156.82,28.39 156.82,29.44 v3(156.28,29.98)
TCM_LPC_CLK: length 4.3
  TOP w0.102: UW1.21 91.3,24.85 91.22,24.77 RW2.1 90.29,24.77 89.06,26 v2(89.06,26.11)
TCM_SERIRQ: length 46.9
  TOP w0.102: v3(78.14,32.55) RB1.1 ; UW1.27 94.14,20.95 94.39,20.69 94.39,19.21 RW7.2 96.71,16.89 UW2.4 97.56,16.89 98.38,17.71 100.08,17.71 101.2,18.83 101.2,21.37 101.43,21.6 101.43,21.63 101.43,27.37 97.57,31.23 96.98,31.23 v2(96.8,31.41) v3(95.71,32.5)
  IN2 w0.127: v3(95.71,32.5) 78.19,32.5 v3(78.14,32.55)
TON_DDR: length 7.5
  TOP w0.254: v3(156.28,30.74) 156.34,30.74 156.85,30.23 v2(156.85,29.88) 156.85,29.79 156.51,29.45 155.94,29.45 155.94,29.44 155.22,29.44 155.21,29.45 155.03,29.45 155.03,29.44 153.86,29.44 153.63,29.22 153.63,28.64 153.63,28.64 153.63,27.91 PR408.2
  BOTTOM w0.203: v3(156.28,30.74) 155.96,31.05 PU303.9
TP2_CORE_VCC_S0IX: length 1.8
  TOP w0.102: v3(106.53,80.11) 106.53,80.07 T20.1
  BOTTOM w0.102: UC4.AA22 107.53,79.72 107.14,80.11 v3(106.53,80.11)
TP_CLK: length 247.7
  TOP w0.102: v3(219.69,95.98) 219.97,96.26 D1.3 220.62,99.11 219.58,100.15 C3.1 218.73,99.4 218.73,97.54 217.89,96.69 JTP1.3 ; RB14.1 v1(73.82,7.96) 74.58,8.72 RB8.1 74.96,9.12 74.53,9.56 UB1.87 v3(74.53,15.57)
  IN2 w0.127: v3(219.69,95.98) 219.62,95.91 219.62,92.26 216.8,89.44 182.03,89.44 174.8,82.21 174.8,64.22 182.52,56.5 182.52,45.29 180.38,43.15 180.38,33.58 176.77,29.97 176.77,26.21 164.32,13.76 129.5,13.76 126.39,16.87 110.12,16.87 109.42,17.57 104.32,17.57 102.24,15.49 94.38,15.49 91.62,18.25 88.15,18.25 87.63,17.74 84.75,17.74 84.32,18.17 78.56,18.17 77.59,17.2 75.95,17.2 74.53,15.78 v3(74.53,15.57)
TP_CORE_V1P05_S4: length 1.1
  TOP w0.102: T21.1 110.02,76.67 v3(109.65,76.31)
  BOTTOM w0.102: UC4.AF30 110.02,75.93 v3(109.65,76.31)
TP_DATA: length 244.1
  TOP w0.102: v3(75.17,15.66) 75.17,13.51 74.93,13.27 UB1.88 74.93,11.26 75.14,11.05 75.14,10.6 v2(75.44,10.3) 75.85,9.89 RB9.1 76.36,8.21 76.36,7.5 75.73,6.87 RB15.1 ; JTP1.2 217.81,95.69 218.98,94.52 C4.1 219.37,94.91 218.69,95.59 D1.2 219.03,96.61 v3(219.64,96.61)
  IN2 w0.127: v3(75.17,15.66) 76.21,16.7 77.83,16.7 78.8,17.66 84.11,17.66 84.54,17.23 88.02,17.23 88.53,17.75 91.41,17.75 94.17,14.98 102.45,14.98 104.53,17.06 109.21,17.06 109.9,16.37 126.18,16.37 129.29,13.25 164.53,13.25 177.27,26 177.27,29.7 180.89,33.32 180.89,42.94 183.03,45.08 183.03,56.71 175.31,64.43 175.31,82 182.24,88.93 217.01,88.93 220.13,92.05 220.13,96.22 219.74,96.61 v3(219.64,96.61)
TP_L: length 211.5
  TOP w0.102: v3(113.42,17.59) 113.42,14.9 112.75,14.23 112.75,12.05 v2(112.75,9.6) SW3.2 SW3.1 ; JTP1.6 217.55,99.69 217.99,100.14 217.99,100.74 C6.1 219.97,101.76 221.42,101.76 v3(221.53,101.65)
  IN2 w0.127: v3(221.53,101.65) 221.02,101.65 220.09,100.72 220.09,97.72 219.1,96.73 219.1,92.46 216.62,89.98 181.85,89.98 174.29,82.42 174.29,64.01 182.01,56.29 182.01,45.5 179.88,43.36 179.88,33.79 160.35,14.27 129.71,14.27 126.59,17.4 113.61,17.4 v3(113.42,17.59)
TP_R: length 124.3
  TOP w0.102: v3(221.55,101.05) 221.06,101.53 220.03,101.53 219.57,101.07 C5.1 218.67,101.07 218.22,100.63 218.22,99.95 216.96,98.69 JTP1.5 ; v3(184.5,6.82) SW4.2 SW4.1
  IN2 w0.127: v3(221.55,101.05) 220.9,101.05 220.48,100.62 220.48,91.73 206.92,78.16 206.92,67.9 209.14,65.68 209.14,31.44 184.51,6.82 v3(184.5,6.82)
TP_VCC: length 6.6
  TOP w0.508: C1.1 R1.2 R2.2 218.89,93.62 218.4,94.12 218.4,94.49 217.91,94.98 v3(217.45,94.98) 217.16,94.69 JTP1.1
  BOTTOM w0.102: v3(217.45,94.98) v1(217.45,95.88)
U3RXDN0: length 10.5
  BOTTOM w0.102: LS2.3 22.33,47.64 22.17,47.8 21.98,47.8 21.72,48.06 21.61,48.06 21.43,47.87 DS1.9 DS1.1 19.91,47.87 19.77,48.01 19.62,48.01 v4(19.06,48.57) 18.21,49.42 14.98,49.42 14.3,48.74 14.12,48.74 13.85,48.47 JUSB1.5
U3RXDP0: length 10.7
  BOTTOM w0.102: JUSB1.6 13.85,49.11 14,48.95 14.21,48.95 14.89,49.64 v4(17.97,49.64) 18.3,49.64 19.71,48.23 19.77,48.23 19.91,48.37 DS1.2 DS1.8 21.57,48.37 21.67,48.27 21.81,48.27 22.06,48.02 22.16,48.02 22.27,48.14 LS2.2
U3TXDN0: length 11.8
  BOTTOM w0.102: LS1.3 22.04,49.4 21.9,49.54 21.6,49.54 21.43,49.37 DS1.7 DS1.4 20.05,49.37 19.88,49.54 19.62,49.54 19.36,49.81 19.36,50.07 17.94,51.49 v4(17.94,51.49) 15.12,54.31 14.61,54.31 14.26,54.67 14.1,54.67 13.85,54.42 JUSB1.8
U3TXDP0: length 11.9
  BOTTOM w0.102: LS1.2 22.04,49.9 21.9,49.76 21.64,49.76 21.53,49.87 DS1.6 DS1.5 19.99,49.87 19.88,49.76 19.71,49.76 19.57,49.9 19.57,50.16 v4(19.1,50.64) 15.21,54.53 14.7,54.53 13.85,55.38 JUSB1.9
UG_DDR: length 5.3
  TOP w0.102: v3(151.31,30.91) v2(151.31,31.48)
  IN2 w0.762: 149.8,31.06 149.56,31.06 149.45,31.17 145.36,31.17 145.16,31.38
  vias: v3(143.82,31.88) v3(144.48,31.88) v3(150.67,30.91)
UGATE1-1: length 9.8
  IN2 w0.762: 154.34,73.87 154.34,72.5 152.18,70.34 152.18,65.45 152.53,65.1
  vias: v2(152.66,64.8) v3(153.28,64.43) v3(153.93,64.41) v3(154.07,74.71) v3(154.65,74.71)
UGATEG1:
  vias: v1(158.34,83.96)
UGATEG1-1: length 17.6
  IN2 w0.762: 159.74,65.29 162.49,68.04 162.49,81.75
  vias: v3(158.25,63.99) v3(158.78,64.35) v3(161.6,83.24) v3(161.6,82.53)
USB3_REXT0: length 10.9
  TOP w0.102: v3(103.94,85.41) 104.3,85.77 v2(104.3,89.49) 104.3,93.07 104.58,93.35 104.58,94.12 104.3,94.4 RC55.1
  BOTTOM w0.102: UC4.M12 103.66,85.41 v3(103.94,85.41)
USB20_BT_N: length 51.6
  TOP w0.102: v3(181.81,81.14) 181.64,80.97 181.2,80.97 178.24,83.93 168.68,83.93 163.53,89.07 162.2,89.07 RM17.2 ; RS19.1 v3(186.3,59.91)
  IN2 w0.127: v3(181.81,81.14) 182.03,80.92 182.28,80.92 182.61,80.6 182.61,79.96 179.69,77.03 179.69,65.23 183.63,61.29 185.58,59.34 186.2,59.34 186.3,59.44 v3(186.3,59.91)
USB20_BT_P: length 51.5
  TOP w0.102: RM16.2 162.11,88.86 163.44,88.86 168.59,83.71 178.15,83.71 181.11,80.75 181.68,80.75 181.81,80.61 v3(181.81,80.35) ; RS18.1 v3(186.4,58.74)
  IN2 w0.127: v3(181.81,80.35) 181.81,80.53 181.95,80.66 182.17,80.66 182.35,80.49 182.35,80.07 179.42,77.14 179.42,65.12 183.48,61.07 185.47,59.08 186.06,59.08 v3(186.4,58.74)
USB20_BT_R_N: length 11.7
  TOP w0.102: JWLAN1.36 155.75,93.67 155.4,93.33 v4(155.4,92.46) 155.4,92.03 RM14.1 155.43,90.94 155.43,89.82 155.44,89.81 155.44,89.14 155.74,88.85 156.41,88.85 158.71,88.85 158.88,89.02 160.82,89.02 160.9,89.11 RM17.1
USB20_BT_R_P: length 11.7
  TOP w0.102: RM16.1 160.66,88.81 158.97,88.81 158.8,88.63 156.5,88.63 155.65,88.63 155.21,89.06 v4(155.21,89.52) 155.21,90.94 RM15.1 155.18,91.97 155.18,92.73 155.19,92.74 155.19,93.32 154.95,93.55 JWLAN1.38
USB20_N0: length 109.8
  IN2 w0.089: 100.01,85.61 100.03,85.61 100.07,85.64 100.43,85.64 101.84,84.24 102.42,84.24 102.74,83.92 102.74,83.58 v3(102.43,83.27)
  IN2 w0.127: 100.01,85.61 98.51,85.61 97.41,86.71 93.09,86.71 92.25,85.87 90.85,85.87 87.16,82.18 86.09,82.18 85.81,81.9 85.81,81.64 85.3,81.13 83.64,81.13 82.65,82.12 63.77,82.12 62.23,83.66 52.57,83.66 46.09,77.18 46.09,68.24 38.78,60.93 38.78,58.06 37.64,56.92 36.62,56.92 31.19,51.48 31.19,49.27 29.78,47.86 29.78,46.24 29.02,45.49 28.11,45.49 27.9,45.28 v3(27.9,45.13)
  BOTTOM w0.102: v3(102.43,83.27) 102.32,83.16 UC4.K16 ; v3(27.9,45.13) 27.9,45.14 27.58,45.46 25.83,45.46 25.39,45.03 24.98,45.03 24.81,44.86 LS3.4
USB20_N0_L: length 18
  IN2 w0.127: v3(21.26,44.68) 20.61,45.34 20.61,46.34 18.65,48.29 18.65,51.14 17.8,51.99 16.26,51.99 JUSB1.2
  BOTTOM w0.102: LS3.3 22.98,44.86 22.79,45.04 22.44,45.04 21.86,45.61 21.86,46.09 21.16,46.8 v4(20.86,46.8) 20.56,46.8 20.47,46.71 20.47,46.55 DS2.6 21.37,44.79 v3(21.26,44.68)
USB20_N1: length 120.5
  IN2 w0.089: 98.29,84.71 98.31,84.69 98.36,84.69 98.51,84.54 99.31,84.54 99.52,84.76 100.56,84.76 101.46,83.86 101.46,83.37 101.35,83.27 v3(101,83.27)
  IN2 w0.127: v3(28.18,35.41) 28.48,35.71 29.56,35.71 30.72,36.86 30.72,47.56 31.97,48.81 31.97,51.17 36.95,56.14 37.96,56.14 39.55,57.74 39.55,60.59 46.87,67.91 46.87,76.74 53.02,82.89 60.16,82.89 61.19,81.86 62.84,81.86 63.35,81.34 78.92,81.34 78.93,81.33 81.05,81.33 82.03,80.35 86.6,80.35 90.89,84.64 92.26,84.64 93.52,85.9 97.1,85.9 98.29,84.71
  BOTTOM w0.102: v3(28.18,35.41) 27.82,35.76 23.14,35.76 22.63,35.25 22.04,35.25 21.9,35.11 LS4.4 ; v3(101,83.27) 100.9,83.36 UC4.G14
USB20_N1_L: length 13.5
  IN2 w0.127: JUSB2.2 12.4,33.08 12.68,32.8 17.03,32.8 18.68,34.45 18.68,35.14 18.52,35.29 18.04,35.29 17.43,34.68 v3(17.43,34.42)
  BOTTOM w0.102: v3(17.43,34.42) DS3.6 19.25,35.26 19.79,35.26 19.95,35.11 LS4.3
USB20_N2: length 75.5
  IN2 w0.089: 100.44,86.76 100.45,86.76 100.49,86.8 100.95,86.8 101.2,86.55 101.2,86.14 101.81,85.53 101.81,85.44 v3(101.64,85.27)
  IN2 w0.127: 100.44,86.76 98.63,86.76 97.86,87.53 90.17,87.53 85.56,82.92 71.86,82.92 71.07,83.71 69.58,83.71 69.37,83.91 67.51,83.91 67.03,83.43 63.95,83.43 63.7,83.69 62.95,84.43 51.41,84.43 49.44,82.47 48.46,82.47 48.08,82.85 48.08,83.12 48.08,83.12 48.08,83.26 v3(47.84,83.5)
  BOTTOM w0.102: v3(101.64,85.27) 101.61,85.24 UC4.J12 ; v3(47.84,83.5) 48.1,83.76 48.1,83.99 48.86,84.76 48.86,87.07 48.08,87.85 48.08,94.13 48.64,94.69 48.64,96.19 48.96,96.51 49.55,96.51 49.66,96.62 LX1.4
USB20_N2_R: length 7.2
  BOTTOM w0.102: LX1.3 51.36,96.49 52.31,96.49 53.06,97.24 53.96,97.24 55.54,98.82 55.54,99.17 55.39,99.31 55.04,99.31 54.9,99.45 JEDP1.2
USB20_N3: length 137.1
  TOP w0.102: RS17.1 189.05,59.42 188.51,59.42 RS19.2 187.54,59.43 185.31,59.43 182.33,56.45 182.33,53.86 180.23,51.76 179.32,51.76 179.2,51.88 v3(179.2,52.11)
  IN2 w0.089: 104.17,86.1 104.16,86.1 104.12,86.06 103.84,86.06 102.99,86.91 102.54,86.91 102.18,86.55 102.18,86.46 101.94,86.21 v3(101.94,86.21)
  IN2 w0.127: 104.17,86.1 105.22,86.1 106.01,85.31 106.01,84.7 107.51,83.2 112.89,83.2 114.29,81.81 123.51,81.81 123.9,81.41 123.9,80.51 124.12,80.29 124.44,80.29 124.66,80.51 124.66,81.41 125.04,81.79 125.58,81.79 125.96,81.41 125.96,80.51 126.18,80.29 126.49,80.29 126.72,80.51 126.72,81.41 127.1,81.79 127.7,81.79 128.7,82.8 129.42,82.8 129.64,83.02 129.64,83.83 130.02,84.21 130.55,84.21 130.93,83.83 130.93,83.02 131.16,82.8 131.47,82.8 131.7,83.02 131.7,83.83 132.08,84.21 132.61,84.21 132.99,83.83 132.99,83.02 133.21,82.8 133.53,82.8 133.75,83.02 133.75,83.83 134.13,84.21 134.67,84.21 135.05,83.83 135.05,83.02 135.27,82.8 135.59,82.8 135.81,83.02 135.81,83.83 136.19,84.21 136.73,84.21 137.11,83.83 137.11,83.02 137.33,82.8 137.95,82.8 138.56,83.42 140.7,83.42 143.66,86.38 150.48,86.38 150.72,86.62 152.9,86.62 153.55,85.97 163.37,85.97 169.95,79.4 169.95,62.91 176.92,55.94 176.92,53.53 178.57,51.88 178.96,51.88 v3(179.2,52.11)
  BOTTOM w0.102: UC4.H10 v3(101.94,86.21)
USB20_P0: length 109.7
  IN2 w0.089: v3(103.04,83.29) 102.93,83.4 102.93,84 102.5,84.43 101.92,84.43 101.49,84.85 101.28,85.06 100.51,85.84 100.07,85.84 100.03,85.87 100.01,85.87
  IN2 w0.127: v3(27.9,45.87) 28.02,45.75 28.91,45.75 29.51,46.35 29.51,47.97 30.92,49.38 30.92,51.59 36.51,57.18 37.53,57.18 38.51,58.17 38.51,61.04 45.82,68.35 45.82,77.29 52.46,83.93 62.34,83.93 63.88,82.39 82.76,82.39 83.75,81.39 85.19,81.39 85.54,81.75 85.54,82.01 85.98,82.44 87.04,82.44 90.74,86.14 92.14,86.14 92.98,86.98 97.52,86.98 98.62,85.87 100.01,85.87
  BOTTOM w0.102: LS3.1 24.81,45.36 24.93,45.24 25.3,45.24 25.74,45.68 27.71,45.68 v3(27.9,45.87) ; v3(103.04,83.29) 103.03,83.28 UC4.M16
USB20_P0_L: length 17.9
  IN2 w0.127: v3(19.47,44.66) 20.34,45.53 20.34,46.23 18.38,48.18 18.38,51.02 17.69,51.72 16.17,51.72 JUSB1.3
  BOTTOM w0.102: LS3.2 22.98,45.36 22.88,45.26 22.53,45.26 22.08,45.7 22.08,46.18 21.25,47.01 20.47,47.01 20.25,46.8 20.25,46.44 DS2.4 v3(19.47,44.66)
USB20_P1: length 120.6
  IN2 w0.089: 98.48,84.89 98.5,84.88 98.5,84.83 98.59,84.73 99.23,84.73 99.44,84.95 100.64,84.95 101.65,83.94 101.65,83.4 v3(101.81,83.24)
  IN2 w0.127: v3(28.18,36.15) 28.35,35.98 29.45,35.98 30.45,36.97 30.45,47.67 31.71,48.92 31.71,51.28 36.83,56.41 37.85,56.41 39.29,57.85 39.29,60.7 46.61,68.02 46.61,76.85 52.91,83.15 60.27,83.15 61.3,82.13 62.95,82.13 63.46,81.61 79.03,81.61 79.04,81.59 81.16,81.59 82.14,80.62 86.49,80.62 90.78,84.9 92.15,84.9 93.41,86.17 97.21,86.17 98.48,84.89
  BOTTOM w0.102: v3(101.81,83.24) 101.61,83.44 UC4.J14 ; v3(28.18,36.15) 28,35.98 23.05,35.98 22.54,35.47 22.04,35.47 21.9,35.61 LS4.1
USB20_P1_L: length 13.5
  IN2 w0.127: JUSB2.3 13.03,32.53 17.14,32.53 18.94,34.34 18.94,35.25 18.63,35.56 18.2,35.56 v3(17.44,36.32)
  BOTTOM w0.102: LS4.2 19.92,35.61 19.79,35.48 19.25,35.48 DS3.4 v3(17.44,36.32)
USB20_P2: length 75.5
  IN2 w0.089: v3(102.49,85.28) 102.11,85.28 102,85.39 102,85.61 101.39,86.22 101.39,86.63 101.03,86.99 100.5,86.99 100.46,87.03 100.44,87.03
  IN2 w0.127: v3(48.58,83.5) 48.34,83.26 48.34,83.23 48.35,83.23 48.35,82.96 48.57,82.74 49.33,82.74 51.3,84.7 63.06,84.7 64.06,83.7 66.92,83.7 67.4,84.18 69.48,84.18 69.69,83.98 71.18,83.98 71.97,83.19 85.45,83.19 90.06,87.8 97.97,87.8 98.74,87.03 100.44,87.03
  BOTTOM w0.102: v3(48.58,83.5) 48.32,83.76 48.32,83.91 49.08,84.67 49.08,87.16 48.29,87.94 48.29,94.04 48.85,94.6 48.85,96.1 49.05,96.3 49.52,96.3 49.64,96.18 49.76,96.18 49.81,96.12 LX1.1 ; UC4.K12 102.31,85.1 v3(102.49,85.28)
USB20_P2_R: length 7.1
  BOTTOM w0.102: LX1.2 51.38,96.27 52.4,96.27 53.15,97.02 54.05,97.02 55.75,98.73 55.75,99.21 55.9,99.36 JEDP1.4
USB20_P3: length 137.1
  TOP w0.102: v3(179.2,51.37) 179.37,51.55 180.32,51.55 182.54,53.77 182.54,56.36 185.4,59.22 187.54,59.22 RS18.2 188.48,59.2 189.05,59.2 RS16.1
  IN2 w0.089: 104.17,85.84 104.16,85.84 104.12,85.87 103.76,85.87 102.91,86.72 102.62,86.72 102.37,86.47 102.37,86.19 102.45,86.11 102.71,86.11 v3(102.84,86.24)
  IN2 w0.127: 104.17,85.84 105.11,85.84 105.75,85.2 105.75,84.59 107.4,82.94 112.78,82.94 114.18,81.54 123.39,81.54 123.63,81.3 123.63,80.4 124.01,80.02 124.55,80.02 124.93,80.4 124.93,81.3 125.15,81.53 125.47,81.53 125.69,81.3 125.69,80.4 126.07,80.02 126.6,80.02 126.98,80.4 126.98,81.3 127.21,81.53 127.81,81.53 128.81,82.53 129.53,82.53 129.91,82.91 129.91,83.72 130.13,83.94 130.44,83.94 130.67,83.72 130.67,82.91 131.05,82.53 131.58,82.53 131.96,82.91 131.96,83.72 132.19,83.94 132.5,83.94 132.72,83.72 132.72,82.91 133.1,82.53 133.64,82.53 134.02,82.91 134.02,83.72 134.24,83.94 134.56,83.94 134.78,83.72 134.78,82.91 135.16,82.53 135.7,82.53 136.08,82.91 136.08,83.72 136.3,83.94 136.62,83.94 136.84,83.72 136.84,82.91 137.22,82.53 138.06,82.53 138.68,83.15 140.81,83.15 143.77,86.11 150.59,86.11 150.83,86.36 152.79,86.36 153.44,85.71 163.26,85.71 169.68,79.29 169.68,62.8 176.65,55.83 176.65,53.42 178.46,51.61 178.96,51.61 v3(179.2,51.37)
  BOTTOM w0.102: v3(102.84,86.24) 102.38,85.78 UC4.K10
USB20_R_N3: length 3.5
  TOP w0.102: RS17.2 190.63,59.42 v4(191.28,59.42) 192.91,59.42 193.05,59.57 US2.14
USB20_R_P3: length 3.6
  TOP w0.102: US2.15 193.05,59.07 192.91,59.21 191.56,59.21 191.55,59.19 191.02,59.19 191,59.21 190.65,59.21 RS16.2
USB_EN#: length 238.6
  TOP w0.102: v3(187.74,51.44) 187.74,51.57 187.87,51.7 US3.4 ; UB1.84 v3(73.33,15.8)
  IN2 w0.127: v3(187.74,51.44) 187.74,50.82 186.44,49.52 186.44,43.86 183.94,41.35 183.94,32.03 180.32,28.42 180.32,24.19 165.02,8.89 129.35,8.89 125.22,13.01 v3(115.07,13.01) ; v3(73.33,15.8) 71.44,15.8 70.87,16.37 66.7,16.37 66.14,15.8 63.96,15.8 49.9,29.86 43.4,29.86 37.2,36.06 37.2,45.31 38.06,46.16 v3(38.06,47.27)
  BOTTOM w0.102: US1.4 17.41,42.64 18.69,42.64 19.13,42.2 21.89,42.2 23.55,43.85 25.58,43.85 26.01,44.28 29.07,44.28 v2(33.08,48.3) 35.16,50.38 36.69,50.38 38.06,49.01 v3(38.06,47.27) ; v3(73.33,15.8) 73.52,15.8 74.46,14.87 78.55,14.87 80.58,16.9 86.9,16.9 87.48,17.48 89.7,17.48 90.92,16.26 92.26,16.26 93.05,15.48 100.39,15.48 101.39,14.47 111.64,14.47 111.65,14.46 113.62,14.46 v3(115.07,13.01)
USB_HUB_BT_N3: length 74.2
  TOP w0.102: v3(180.44,55.8) 180.44,55.59 180.53,55.51 180.98,55.51 181.35,55.88 181.35,57.2 186.95,62.8 187.78,62.8 187.79,62.81 188.32,62.81 188.33,62.8 192.3,62.8 192.53,63.03 196.1,63.03 196.8,62.32 196.8,61.36 196.95,61.22 US2.7 ; v3(155.96,89.23) RM14.2
  IN2 w0.127: v3(155.96,89.23) 155.53,89.23 155.43,89.12 155.43,89.02 155.64,88.81 164.55,88.81 167.59,85.76 168.44,85.76 173.27,80.93 173.27,64.19 179.93,57.54 179.93,55.69 180.06,55.56 180.2,55.56 v3(180.44,55.8)
USB_HUB_BT_P3: length 74
  TOP w0.102: RM15.2 v3(154.68,89.23) ; v3(180.44,55.05) 180.68,55.29 181.07,55.29 181.57,55.79 181.57,57.11 187.04,62.58 v4(188.05,62.58) 192.39,62.58 192.62,62.81 196.01,62.81 196.59,62.23 196.59,61.36 196.45,61.22 US2.8
  IN2 w0.127: v3(180.44,55.05) 180.2,55.29 179.95,55.29 179.66,55.58 179.66,57.43 173.01,64.08 173.01,80.82 168.33,85.49 167.48,85.49 164.44,88.54 155.53,88.54 155.16,88.91 155.16,89.04 154.97,89.23 v3(154.68,89.23)
USB_HUB_N1: length 14.5
  TOP w0.102: US2.11 194.95,61.25 194.84,61.35 194.84,61.85 v3(194.97,61.97)
  IN2 w0.127: v3(194.97,61.97) 194.79,62.15 194.79,62.51 194.47,62.84 193.57,62.84 192.54,61.8 192.54,58.66 189.49,55.61 188.88,55.61 v3(188.64,55.85)
  BOTTOM w0.102: v3(188.64,55.85) 188.88,55.61 189.26,55.61 189.66,56 JSB1.4
USB_HUB_P1: length 14.5
  TOP w0.102: US2.12 194.45,61.17 194.63,61.36 194.63,61.74 194.4,61.97 v3(194.22,61.97)
  IN2 w0.127: v3(188.64,55.1) 188.88,55.34 189.6,55.34 192.81,58.55 192.81,61.69 193.68,62.57 194.36,62.57 194.52,62.4 194.52,62.09 194.4,61.97 v3(194.22,61.97)
  BOTTOM w0.102: JSB1.3 189.65,55 189.26,55.39 188.93,55.39 v3(188.64,55.1)
USB_OC0#: length 338.4
  TOP w0.102: v3(107.6,28.05) 111.92,23.73 v3(111.92,12.96) ; RS20.2 v3(187.1,56.75)
  IN2 w0.127: v3(36.56,51.06) 37.09,51.06 42.36,56.33 42.36,59.69 45.88,63.2 47.71,63.2 49.51,65 49.51,68.01 49.47,68.05 49.7,68.27 49.7,72.36 51.9,74.56 57.64,74.56 57.95,74.86 62.48,74.86 64.81,77.19 68.7,77.19 v3(68.88,77.01) ; v3(187.1,56.75) 187.1,52.71 188.25,51.57 188.25,50.16 187.05,48.97 187.05,43.84 184.19,40.98 184.19,31.93 180.58,28.31 180.58,24.08 165.12,8.63 129.24,8.63 125.29,12.58 112.3,12.58 v3(111.92,12.96)
  BOTTOM w0.102: UC4.C20 98.74,81.03 98.46,81.03 98.32,81.18 98.13,81.18 98.01,81.06 95.36,81.06 95.13,81.29 95.13,83.39 94.87,83.65 94.08,83.65 93.19,84.54 90.12,84.54 RC59.2 89.01,83.43 86.32,83.43 85.28,82.38 73.71,82.38 73.04,81.72 70.99,81.72 68.88,79.62 v3(68.88,77.01) 68.88,76.94 68.34,76.4 68.34,72.23 68.89,71.68 68.89,70.47 69.94,69.42 69.94,58.26 61.66,49.97 61.66,46.03 60.44,44.82 60.44,38.93 61.19,38.19 62.78,36.59 62.96,36.41 62.96,35.27 63.99,34.24 64.62,34.24 65.02,33.84 68.96,33.84 71.03,31.77 82.64,31.77 84.38,30.03 101.2,30.03 102.72,28.51 107.14,28.51 v3(107.6,28.05) ; v3(36.56,51.06) v2(35.19,51.06) 28.63,44.51 25.92,44.51 25.48,44.08 23.45,44.08 21.8,42.43 19.23,42.43 18.79,42.87 16.81,42.87 16.14,42.2 RS2.2
USB_OC1#: length 7.9
  BOTTOM w0.102: UC4.B20 98.22,80.85 95.28,80.85 94.92,81.21 94.92,81.37 94.92,81.38 94.92,83.31 94.78,83.45 93.38,83.45 RC61.2
USB_PLL_MON: length 12
  TOP w0.102: v3(103.93,84.74) 105.19,86 105.19,91.73 v2(104.91,92.01) 104.91,92.82 105.19,93.1 105.19,94.55 105.19,94.55 RC62.2
  BOTTOM w0.102: UC4.M13 103.7,84.74 v3(103.93,84.74)
USB_RCOMP: length 12.5
  TOP w0.254: v3(99.92,87.48) 99.92,87.32 99.37,86.78 98.3,86.78 97.39,87.69
  TOP w0.381: 97.39,87.69 96.55,88.52 v2(96.55,92.77) 96.55,94.87 RC60.2
  BOTTOM w0.254: UC4.C7 99.12,87 99.41,87.29 UC4.D6 99.84,87.56 v3(99.92,87.48)
VCIN0_PH1: length 163
  TOP w0.203: v3(85.25,21.22) 85.25,19.47 83.85,18.06 RB20.1 82.48,18.06 PR110.2 82.28,17.86 81.36,17.86 80.93,18.3 80.93,18.4 80.76,18.57 79.76,18.57 UB1.109
  TOP w0.254: v3(144.53,46.62) 143.38,47.78 143.38,49.39 139.03,53.73 136.78,53.73 127.74,62.77 127.74,74.58 126.93,75.4 124.16,75.4 122.92,76.64 122.92,77.42 122.68,77.66 122.26,77.66 121.88,77.27 119.49,77.27 119.26,77.04 118.65,77.04 PH100.1
  IN2 w0.203: v3(85.25,21.22) 85.55,21.52 86.52,21.52 88.1,23.1 92.33,23.1 92.74,22.69 97.79,22.69 98.85,21.62 99.01,21.62 100.11,21.62 100.49,22 149.17,22 152.02,24.85 155.66,24.85 159.67,28.86 159.67,37.93 152.37,45.23 145.92,45.23 v3(144.53,46.62)
VCIN1_AC_IN: length 339.6
  TOP w0.203: 78.34,19.38 78.75,18.97 UB1.110
  TOP w0.254: v3(106.38,13.37) 107.27,14.26 v3(107.27,25.18) ; PR228.2 PR229.1 200.5,73.54 200.88,73.92 200.88,75.08 v3(200.46,75.5) ; v3(82.39,81.05) 82.8,80.65 DC1.1 ; v3(92.59,30.59) 95.16,28.03 v3(95.16,26.86) ; v3(73.34,21.29) 73.34,21.24 74,20.58 77.15,20.58 78.34,19.38
  IN2 w0.254: v3(107.27,25.18) 106.79,25.18 104.66,27.31 99.09,27.31 98.3,26.52 95.49,26.52 v3(95.16,26.86) 94.5,27.52 89.24,27.52 87.82,26.09 85.9,26.09 85.07,25.26 80.93,25.26 79.1,23.43 77.59,23.43 76.21,22.05 74.1,22.05 v3(73.34,21.29) ; v3(106.38,13.37) 106.6,13.59 125.1,13.59 129.48,9.2 164.83,9.2 180,24.38 180,28.55 183.62,32.17 183.62,41.49 185.76,43.62 185.76,57.84 178.73,64.87 178.73,81.56 180.72,83.55 199.47,83.55 201.71,81.31 201.71,78.39 200.82,77.5 200.82,75.85 v3(200.46,75.5)
  BOTTOM w0.203: PU1.5 200.78,74.7 200.46,75.02 v3(200.46,75.5)
  BOTTOM w0.254: v3(82.39,81.05) 81.55,81.05 81.26,81.34 74.14,81.34 73.48,80.68 71.42,80.68 70.25,79.51 70.25,76.82 69.38,75.95 69.38,72.7 69.93,72.15 69.93,70.91 70.98,69.85 70.98,57.82 62.7,49.54 62.7,45.6 61.48,44.38 61.48,39.45 65.98,34.96 69.84,34.96 71.54,33.25 72.78,33.25 73.36,33.84 82.05,33.84 84.81,31.07 87.59,31.07 88.09,30.57 89.64,30.57 90.05,30.97 v2(91.6,30.97) 92.21,30.97 v3(92.59,30.59)
VCIN1_ADP_PROCHOT: length 9.2
  TOP w0.203: UB1.102 80.91,15.77 81.07,15.93 81.83,15.93 82.2,15.57 82.2,15.43 82.71,14.92 RB21.1 PR112.1 v2(85.43,14.92) 85.83,14.92 85.88,14.97 PR113.2 85.88,15.94 84.52,15.94 PR111.2
VCIN1_BATT_DROP: length 56.3
  TOP w0.102: UB1.64 64.95,13.77 66.43,15.25 66.48,15.25 v3(66.91,15.68)
  IN2 w0.127: v3(66.91,15.68) 66.48,15.25 64.16,15.25 49.88,29.53 43.37,29.53 36.95,35.96 36.95,46.23 v3(37.51,46.79)
  BOTTOM w0.102: PR312.2 PC327.1 PR313.1 37.51,46.35 v3(37.51,46.79)
VCIN1_BATT_TEMP: length 259.3
  TOP w0.102: v3(58.65,16.01) v2(59.86,14.8) 60.49,14.17 UB1.63
  IN2 w0.127: v3(58.65,16.01) 61.96,16.01 64.12,13.85 67.37,13.85 68.87,15.35 70.45,15.35 71.02,14.79 75.75,14.79 77.02,16.06 78.09,16.06 79.06,17.03 83.84,17.03 84.37,16.5 91.75,16.5 93.91,14.35 102.83,14.35 104.55,16.06 106.87,16.06 107.32,16.52 108.92,16.52 109.58,15.86 125.97,15.86 129.08,12.75 164.82,12.75 177.78,25.71 177.78,29.49 181.4,33.11 181.4,42.73 183.54,44.86 183.54,56.92 175.81,64.65 175.81,81.79 180.8,86.77 194.75,86.77 v3(194.93,86.95) 201.1,86.95 205.57,82.48 205.57,66.13 v3(205.24,65.79)
  BOTTOM w0.102: v3(194.93,86.95) 197.26,89.29 PR109.2 ; v3(205.24,65.79) 202.67,68.36 201.81,68.36 201.58,68.6 PU1.15
VCORE_GSNS: length 352.1
  TOP w0.203: 152.45,60.67 152.47,60.68 152.67,60.68 152.68,60.67 153.68,60.67 153.88,60.87 PC763.2 ; v3(159.16,60.28) 159.15,60.28 159.09,60.22 158.3,60.22 157.84,60.68 PC709.2
  TOP w0.254: v3(149.41,56.19) 150.02,56.8 151.72,56.8 152.59,57.67 152.59,58.84 153.17,59.42 153.17,59.96 v3(152.47,60.67) 152.45,60.67 ; RC73.1 101.52,75.98 103.05,75.98 103.31,76.23 v3(103.31,76.47) ; v3(117.12,7.86) 116.97,8 116.97,17.58 v3(117.3,17.91)
  IN2 w0.254: v3(103.31,76.47) 102.82,75.98 102.44,75.98 102.22,76.21 101.37,76.21 100.74,75.57 99.96,75.57 97.39,78.14 96.17,78.14 95.78,77.74 93.11,77.74 92.79,77.42 78.58,77.42 78.48,77.52 75.17,77.52 74.29,78.39 74.29,78.88 73.79,79.38 63.23,79.38 63.16,79.45 62.08,79.45 61.34,80.2 52.21,80.2 47.95,75.94 47.95,67.41 40.63,60.09 40.63,56.88 38.67,54.92 37.25,54.92 33.05,50.72 33.05,34.35 42.22,25.18 43.54,25.18 52.15,16.57 52.15,13.52 57.87,7.81 63.48,7.81 64.14,7.15 65.49,7.15 65.95,7.6 69.25,7.6 69.69,7.17 71.35,7.17 73.45,9.27 79.59,9.27 81.23,10.91 84.73,10.91 85.25,10.38 88.48,10.38 91.97,6.89 102.19,6.89 102.71,7.41 114.62,7.41 115.51,8.3 116.67,8.3 v3(117.12,7.86) ; v3(159.16,60.28) 158.99,60.45 158.57,60.45 158.54,60.49 152.67,60.49 152.49,60.67 v3(152.47,60.67)
  BOTTOM w0.203: PU602.12 153.29,61.87 153.25,61.91 152.81,61.91 152.35,61.45 152.35,60.8 152.49,60.67 v3(152.47,60.67) ; v3(159.16,60.28) 159.29,60.41 159.29,61.2 159.02,61.47 PU602.30
  BOTTOM w0.254: v3(117.3,17.91) 117.3,18.24 117.67,18.6 120.35,18.6 128.48,10.47 161.3,10.47 165.41,14.59 165.41,43.7 155.13,53.98 153.05,53.98 151.52,55.51 150.1,55.51 v3(149.41,56.19) ; UC4.N28 103.74,76.94 103.31,76.51 v3(103.31,76.47)
VCORE_VSNS: length 333.8
  TOP w0.254: v3(116.54,18.01) 116.41,17.89 116.41,7.86 v3(116.37,7.81) ; RC72.2 104.46,76.02 104.25,76.23 104.2,76.23 103.96,76.46 v3(103.94,76.46)
  IN2 w0.254: v3(103.94,76.46) 103.94,76.59 103.56,76.97 102.39,76.97 102.01,76.59 101.21,76.59 100.58,75.95 100.11,75.95 97.55,78.52 96.01,78.52 95.62,78.12 92.96,78.12 92.63,77.8 78.73,77.8 78.64,77.9 75.33,77.9 74.67,78.55 74.67,79.04 73.95,79.76 63.38,79.76 63.31,79.84 62.24,79.84 61.5,80.58 52.05,80.58 47.57,76.1 47.57,67.57 40.25,60.25 40.25,57.04 38.52,55.3 37.09,55.3 32.67,50.88 32.67,34.19 42.06,24.8 43.38,24.8 51.77,16.41 51.77,13.37 57.71,7.43 63.32,7.43 63.98,6.77 65.65,6.77 66.1,7.22 69.1,7.22 69.53,6.79 71.51,6.79 73.6,8.89 79.75,8.89 81.39,10.52 84.57,10.52 85.1,10 88.32,10 91.81,6.51 102.35,6.51 102.87,7.03 114.78,7.03 115.56,7.81 v3(116.37,7.81)
  BOTTOM w0.254: PC756.1 150.55,59 PR740.1 149.67,59.01 PC762.2 149.04,59.03 147.95,57.93 147.95,56.41 149.23,55.13 151.37,55.13 152.89,53.6 154.97,53.6 165.03,43.55 165.03,14.74 161.14,10.85 128.63,10.85 120.51,18.98 117.51,18.98 v3(116.54,18.01) ; v3(103.94,76.46) 104.26,76.78 104.26,76.78 104.45,76.97 UC4.P28
